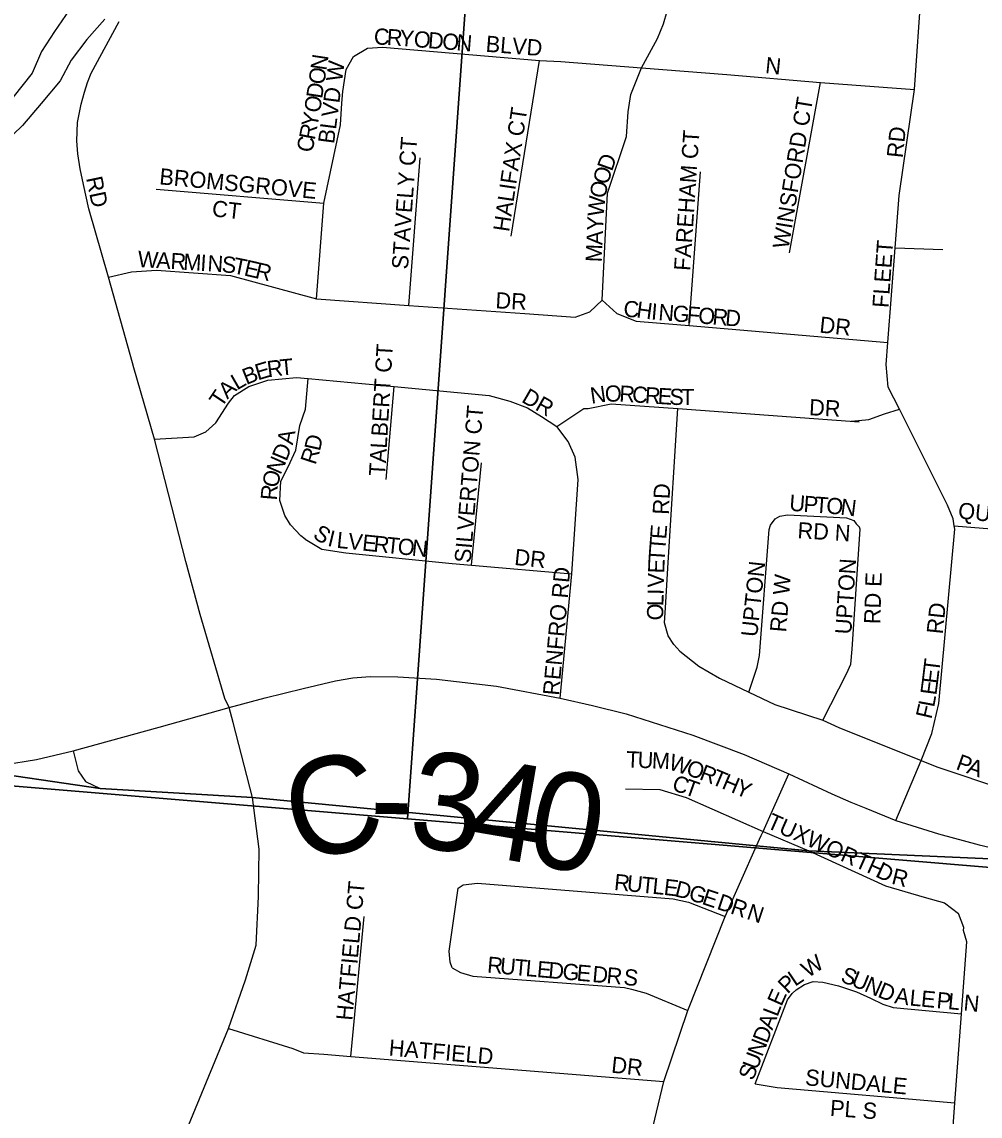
# Model space of a CAD drawing. Extents: x 0 to 34, y 0 to 22.
# Drawn here: x 7.534 to 8.094, y 17.781 to 18.421 of the extents above; entities that cross this region are included whole.
import ezdxf

# ---------------------------------------------------------------- set-up
doc = ezdxf.new("R2010")
doc.units = 0
for name, color, linetype in [('GM_X_City_Street', 7, 'Continuous'), ('GM_X_City_Street_Text', 7, 'Continuous'), ('GM_X_County_Road', 7, 'Continuous'), ('GM_X_County_Road_Text', 7, 'Continuous'), ('GM_X_Major_River', 7, 'Continuous'), ('GM_X_Section', 7, 'Continuous'), ('GM_X_Township', 7, 'Continuous'), ('GM_X_Township_Road', 7, 'Continuous'), ('GM_X_Township_Subdivision', 7, 'Continuous'), ('GM_X_Township_Subdivision_Text', 7, 'Continuous')]:
    doc.layers.add(name, color=color, linetype=linetype)

msp = doc.modelspace()

# ---------------------------------------------------------------- linework, layer by layer
at = {"layer": 'GM_X_City_Street'}
for points in [[(7.87314, 18.25833), (7.87628, 18.32088), (7.88732, 18.35412), (7.88831, 18.36842), (7.88992, 18.37867), (7.8962, 18.39423), (7.90541, 18.41133), (7.9089, 18.42002), (7.91116, 18.42728), (7.91346, 18.4521), (7.91708, 18.51688), (7.91889, 18.54186), (7.91998, 18.57654), (7.92253, 18.59091), (7.92773, 18.60485), (7.93089, 18.61124), (7.9387, 18.62398)], [(8.04039, 18.2075), (8.03909, 18.22079), (8.04009, 18.23371), (8.04437, 18.28898), (8.04675, 18.31968), (8.05567, 18.38157), (8.05978, 18.44059)], [(7.5994, 18.2188), (7.59855, 18.22178), (7.58458, 18.27192), (7.57307, 18.31187), (7.56994, 18.326), (7.56797, 18.33521), (7.56666, 18.34393), (7.566, 18.35149), (7.56649, 18.36234), (7.56847, 18.37302), (7.57044, 18.38009), (7.57224, 18.38569), (7.57438, 18.39111), (7.59082, 18.42136)], [(7.72785, 18.40081), (7.73591, 18.40574), (7.74462, 18.4064), (7.83652, 18.39851), (7.84901, 18.39785), (7.8962, 18.39423), (7.94602, 18.39029), (8.00076, 18.38568), (8.05567, 18.38157)], [(7.70604, 18.25919), (7.71033, 18.31517), (7.72012, 18.36086), (7.72094, 18.37351), (7.72144, 18.38042), (7.72349, 18.39324), (7.72785, 18.40081)], [(7.81983, 18.29584), (7.83652, 18.39851)], [(7.98257, 18.28608), (8.00076, 18.38568)], [(7.76006, 18.25535), (7.7667, 18.34171)], [(7.92401, 18.24354), (7.93059, 18.33344)], [(7.61246, 18.32322), (7.71033, 18.31517)], [(8.04437, 18.28898), (8.0722, 18.28805)], [(7.58458, 18.27192), (7.59806, 18.27504), (7.61253, 18.27587), (7.65593, 18.2729), (7.70604, 18.25919), (7.76006, 18.25535), (7.82799, 18.25052), (7.85743, 18.2484), (7.86582, 18.25165), (7.87314, 18.25833)], [(7.87314, 18.25833), (7.88167, 18.25056), (7.89293, 18.24616), (7.9167, 18.24415), (7.92401, 18.24354), (8.04009, 18.23371)], [(7.65737, 18.0116), (7.6551, 18.02038), (7.65247, 18.02548), (7.63817, 18.07464), (7.62979, 18.1057), (7.61137, 18.17706), (7.5994, 18.2188)]]:
    msp.add_lwpolyline(points, dxfattribs=at)
at = {"layer": 'GM_X_County_Road'}
for points in [[(7.6551, 18.02038), (7.67615, 18.02597), (7.69834, 18.03139), (7.71725, 18.03583), (7.72744, 18.03764), (7.73747, 18.03847), (7.75375, 18.0383), (7.77627, 18.03682), (7.81129, 18.03271), (7.84861, 18.0258), (7.86752, 18.02153), (7.88712, 18.01651), (7.92611, 18.0042), (7.95605, 17.99275), (7.98227, 17.98158), (8.00743, 17.96991), (8.01844, 17.96498), (8.02732, 17.96136), (8.04475, 17.95429), (8.06973, 17.9464), (8.09357, 17.93998), (8.11592, 17.93484), (8.1322, 17.93242), (8.1521, 17.92995)], [(7.5047, 17.9845), (7.52325, 17.98684), (7.54241, 17.98996), (7.56386, 17.99506), (7.61417, 18.00871), (7.6551, 18.02038)], [(7.66872, 17.96769), (7.65737, 18.0116)], [(7.67231, 17.90988), (7.67232, 17.91019), (7.67255, 17.93741), (7.66872, 17.96769)], [(7.58898, 17.60376), (7.58928, 17.60553), (7.59778, 17.66988), (7.6066, 17.70308), (7.62629, 17.76361), (7.65462, 17.83269), (7.66454, 17.86111), (7.67094, 17.88135), (7.67231, 17.90988)]]:
    msp.add_lwpolyline(points, dxfattribs=at)
at = {"layer": 'GM_X_Major_River'}
for points in [[(7.5824, 18.42262), (7.57179, 18.41088), (7.56269, 18.39875), (7.55623, 18.38661), (7.54524, 18.37335), (7.53424, 18.36047), (7.52325, 18.34986)], [(7.5616, 18.42796), (7.55288, 18.41545), (7.5453, 18.4037), (7.53998, 18.39119), (7.5286, 18.37679)]]:
    msp.add_lwpolyline(points, dxfattribs=at)
at = {"layer": 'GM_X_Section'}
for points in [[(7.32396, 19.01244), (7.83199, 18.97493), (7.7594, 17.95531), (7.25608, 17.99704)], [(7.83199, 18.97493), (8.33817, 18.93281), (8.26119, 17.91328), (7.7594, 17.95531)], [(7.25608, 17.99704), (7.7594, 17.95531), (8.26119, 17.91328), (8.28732, 17.91243), (8.21553, 16.97509), (7.19182, 17.04453)]]:
    msp.add_lwpolyline(points, close=True, dxfattribs=at)
at = {"layer": 'GM_X_Township'}
for points in [[(5.51769, 18.13119), (5.87625, 18.1039), (6.03605, 18.09206), (6.63383, 18.04603), (6.72474, 18.03863), (6.7448, 18.03814), (6.76124, 18.03764), (6.90082, 18.02498), (7.39535, 17.98733), (7.4612, 17.98313), (7.48383, 17.98347), (7.50256, 17.98423), (7.57966, 17.97294), (7.66873, 17.96768), (7.96341, 17.93943), (7.99401, 17.9365), (8.15736, 17.9293), (8.25091, 17.92059), (8.28461, 17.91779), (8.63956, 17.89017), (9.29091, 17.83808), (9.37362, 17.83148), (9.4, 17.82945)], [(9.4, 17.82945), (9.37362, 17.83148), (9.29091, 17.83808), (8.63956, 17.89017), (8.28461, 17.91779), (8.25091, 17.92059), (8.15736, 17.9293), (7.99401, 17.9365), (7.96341, 17.93943), (7.66873, 17.96768), (7.57966, 17.97294), (7.50256, 17.98423), (7.48383, 17.98347), (7.4612, 17.98313), (7.39535, 17.98733), (6.90082, 18.02498), (6.76124, 18.03764), (6.7448, 18.03814), (6.72474, 18.03863), (6.63383, 18.04603), (6.03605, 18.09206), (5.87625, 18.1039), (5.51769, 18.13119)]]:
    msp.add_lwpolyline(points, dxfattribs=at)
at = {"layer": 'GM_X_Township_Road'}
msp.add_lwpolyline([(7.56386, 17.99506), (7.5668, 17.98336), (7.57116, 17.97705), (7.57966, 17.97294), (7.66872, 17.96769)], dxfattribs=at)
at = {"layer": 'GM_X_Township_Subdivision'}
for points in [[(7.61137, 18.17706), (7.63466, 18.17846), (7.64153, 18.18139), (7.6473, 18.18662), (7.65469, 18.19828), (7.65815, 18.20275), (7.6666, 18.20796), (7.67765, 18.21158), (7.69435, 18.21321), (7.70132, 18.21256), (7.75144, 18.20788), (7.80713, 18.20268), (7.81921, 18.19945), (7.82938, 18.19549), (7.83764, 18.19042), (7.84663, 18.18458)], [(7.69957, 18.11867), (7.69695, 18.12061), (7.69098, 18.12716), (7.68766, 18.13253), (7.68477, 18.14131), (7.68533, 18.1527), (7.68963, 18.16099), (7.69396, 18.1708), (7.69647, 18.1852), (7.69966, 18.19464), (7.70132, 18.21256)], [(7.74677, 18.15363), (7.75144, 18.20788)], [(8.04475, 17.95429), (8.05954, 17.98931), (8.06585, 18.00502), (8.06995, 18.02267), (8.07925, 18.12446), (8.07888, 18.12659), (8.07821, 18.13055), (8.07493, 18.13858), (8.04685, 18.19461), (8.04039, 18.2075)], [(7.84663, 18.18458), (7.86234, 18.19511), (7.865, 18.19507), (7.87832, 18.1979), (7.91731, 18.19504), (8.02338, 18.18725), (8.01883, 18.18771), (8.02909, 18.18868), (8.03825, 18.19196), (8.04685, 18.19461)], [(7.91845, 18.0533), (7.9151, 18.05715), (7.91177, 18.06214), (7.90962, 18.06977), (7.91014, 18.0785), (7.9117, 18.10506), (7.91731, 18.19504)], [(7.84861, 18.0258), (7.85543, 18.09845), (7.85902, 18.15361), (7.85734, 18.16655), (7.85332, 18.17573), (7.84663, 18.18458)], [(7.79678, 18.10343), (7.80267, 18.16339)], [(7.9589, 18.02921), (7.96381, 18.04385), (7.96506, 18.05066), (7.97079, 18.12426), (7.97159, 18.12691), (7.97431, 18.13066)], [(7.97431, 18.13066), (7.97699, 18.13214), (7.98155, 18.13283), (8.01603, 18.13115), (8.02018, 18.12956), (8.02166, 18.12764)], [(8.00216, 18.01282), (8.01608, 18.04036), (8.01844, 18.04564), (8.01934, 18.05437), (8.02389, 18.12457), (8.02353, 18.12571), (8.02166, 18.12764)], [(8.07888, 18.12659), (8.13236, 18.12218), (8.18831, 18.11757), (8.2432, 18.11304)], [(7.69957, 18.11867), (7.70933, 18.11282), (7.72333, 18.11069), (7.78542, 18.1044), (7.79678, 18.10343), (7.85543, 18.09845)], [(7.91845, 18.0533), (7.92969, 18.04438), (7.94171, 18.03735), (7.9589, 18.02921), (7.97408, 18.02203), (8.00216, 18.01282), (8.01153, 18.00854), (8.05954, 17.98931), (8.06875, 17.98553), (8.10886, 17.97221), (8.15095, 17.96188), (8.23009, 17.95456)], [(7.96608, 17.94542), (7.96717, 17.94786), (7.98227, 17.98158)], [(7.88681, 17.97276), (7.90682, 17.9724), (7.92221, 17.96767), (7.96717, 17.94786)], [(7.90411, 17.56419), (7.89935, 17.57452), (7.89173, 17.59591), (7.89107, 17.602), (7.8894, 17.6157), (7.89053, 17.63885), (7.89332, 17.68094), (7.89454, 17.69917), (7.89971, 17.76176), (7.90926, 17.80167), (7.92328, 17.84308), (7.945, 17.89819), (7.96341, 17.93943), (7.96608, 17.94542)], [(7.96717, 17.94786), (7.99401, 17.9365), (8.03877, 17.91596), (8.06134, 17.90939), (8.07324, 17.90611), (8.08145, 17.89996)], [(7.78885, 17.91469), (7.79191, 17.91654), (7.80026, 17.91755), (7.91459, 17.90851), (7.92365, 17.90646), (7.945, 17.89819)], [(7.78544, 17.86803), (7.78436, 17.87147), (7.78371, 17.87793), (7.78885, 17.91469)], [(7.72619, 17.81631), (7.734, 17.89809)], [(8.05394, 17.57175), (8.06211, 17.72575), (8.06332, 17.72991), (8.06642, 17.73403), (8.06912, 17.73665), (8.0726, 17.74115), (8.07654, 17.75059), (8.07937, 17.78927), (8.08318, 17.84124), (8.08626, 17.88336), (8.08428, 17.88993), (8.0845, 17.89175), (8.08145, 17.89996)], [(7.78544, 17.86803), (7.79033, 17.86529), (7.7975, 17.86328), (7.88608, 17.85655), (7.89024, 17.85572), (7.89892, 17.8533), (7.92328, 17.84308)], [(7.99148, 17.85829), (7.99643, 17.86011), (8.00211, 17.85964), (8.01118, 17.85759), (8.02173, 17.85401), (8.03001, 17.85046), (8.03716, 17.84692), (8.04319, 17.84493), (8.08318, 17.84124)], [(7.9625, 17.80026), (7.98148, 17.84933), (7.98419, 17.85309), (7.9865, 17.85533), (7.99148, 17.85829)], [(7.65462, 17.83269), (7.6922, 17.8209), (7.6986, 17.81852), (7.71034, 17.81757), (7.72619, 17.81631), (7.90926, 17.80167)], [(7.9625, 17.80026), (7.97534, 17.79816), (8.07937, 17.78927)]]:
    msp.add_lwpolyline(points, dxfattribs=at)

# ---------------------------------------------------------------- texts
at = {"layer": 'GM_X_City_Street_Text'}
for s, height, rotation, p in [('C', 0.00947, 358.2025, (7.73957, 18.40785)), ('R', 0.00947, 355.94034, (7.74697, 18.40762)), ('Y', 0.00947, 355.53591, (7.75443, 18.40709)), ('O', 0.00947, 355.53591, (7.76273, 18.40644)), ('D', 0.00947, 355.51411, (7.77104, 18.40579)), ('O', 0.00947, 355.54485, (7.77935, 18.40514)), ('N', 0.00947, 355.53591, (7.78766, 18.40449)), ('BLVD', 0.00947, 355.48872, (7.80479, 18.40367)), ('N', 0.00947, 81.43253, (7.7119, 18.39233)), ('BLVD W', 0.00947, 82.61454, (7.71638, 18.34951)), ('N', 0.00947, 354.29373, (7.96816, 18.39117)), ('O', 0.00947, 81.43253, (7.71066, 18.38409)), ('D', 0.00947, 81.43253, (7.70942, 18.37585)), ('O', 0.00947, 81.29572, (7.70815, 18.36759)), ('WINSFORD CT', 0.0094697, 80.74043, (7.98206, 18.28802)), ('HALIFAX CT', 0.00947, 81.57243, (7.81872, 18.298)), ('Y', 0.00947, 79.13593, (7.70652, 18.35902)), ('R', 0.00947, 79.13486, (7.70511, 18.35166)), ('RD', 0.00947, 83.99338, (8.04883, 18.34124)), ('C', 0.00947, 79.12822, (7.70369, 18.34429)), ('STAVELY CT', 0.00947, 85.914, (7.75954, 18.27619)), ('FAREHAM CT', 0.00947, 86.14289, (7.92453, 18.27535)), ('D', 0.00947, 70.20452, (7.87882, 18.33331)), ('BROMSGROVE', 0.00947, 354.64262, (7.61398, 18.32617)), ('O', 0.00947, 73.11369, (7.87644, 18.32545)), ('RD', 0.00947, 281.88403, (7.57139, 18.32976)), ('O', 0.00947, 78.93201, (7.87491, 18.31752)), ('CT', 0.00947, 353.66247, (7.64471, 18.30748)), ('W', 0.00947, 84.75034, (7.87395, 18.30699)), ('Y', 0.00947, 87.65951, (7.87362, 18.29879)), ('A', 0.00947, 87.65951, (7.87328, 18.29046)), ('M', 0.00947, 87.65951, (7.87287, 18.28047)), ('FLEET', 0.00947, 85.91142, (8.04049, 18.25368)), ('W', 0.00947, 356.48345, (7.60142, 18.27785)), ('A', 0.00947, 356.50235, (7.61224, 18.27718)), ('R', 0.00947, 356.47668, (7.62055, 18.27667)), ('M', 0.00947, 356.49946, (7.62804, 18.27621)), ('I', 0.00947, 356.45639, (7.63802, 18.2756)), ('N', 0.00947, 356.50235, (7.64219, 18.27534)), ('S', 0.00947, 354.44439, (7.65041, 18.27484)), ('T', 0.00947, 348.75436, (7.6568, 18.27423)), ('E', 0.00947, 347.10369, (7.66327, 18.27295)), ('R', 0.00947, 346.99446, (7.66976, 18.27146)), ('DR', 0.00947, 356.98902, (7.81057, 18.25368)), ('C', 0.00947, 358.29961, (7.88552, 18.24856)), ('H', 0.00947, 352.15117, (7.89275, 18.24836)), ('I', 0.00947, 355.07323, (7.90153, 18.24717)), ('N', 0.00947, 355.28569, (7.90572, 18.24681)), ('G', 0.00947, 355.30818, (7.91403, 18.24612)), ('F', 0.00947, 355.29535, (7.92234, 18.24544)), ('O', 0.00947, 355.30818, (7.92898, 18.24489)), ('R', 0.00947, 355.30696, (7.93729, 18.24421)), ('D', 0.00947, 355.29625, (7.94476, 18.2436)), ('DR', 0.00947, 353.98321, (7.99983, 18.2395))]:
    msp.add_text(s, height=height, rotation=rotation, dxfattribs=at).set_placement(p)
at = {"layer": 'GM_X_County_Road_Text'}
for s, rotation, p in [('C', 13.17102, (7.69516, 17.92923)), ('3', 353.66441, (7.75885, 17.93921)), ('4', 350.26304, (7.79275, 17.93547)), ('0', 349.96278, (7.82717, 17.92957)), ('-', 359.13349, (7.73695, 17.93947))]:
    msp.add_text(s, height=0.05682, rotation=rotation, dxfattribs=at).set_placement(p)
at = {"layer": 'GM_X_Township_Subdivision_Text'}
for s, height, rotation, p in [('TALBERT CT', 0.00947, 86.5928, (7.7462, 18.15534)), ('T', 0.00947, 5.36263, (7.68519, 18.21428)), ('B', 0.00947, 21.71573, (7.66509, 18.20876)), ('E', 0.00947, 16.70709, (7.67185, 18.21146)), ('R', 0.00947, 7.62192, (7.67785, 18.21329)), ('L', 0.00947, 29.89061, (7.65964, 18.20559)), ('T', 0.00947, 56.09781, (7.65065, 18.19515)), ('A', 0.00947, 43.00589, (7.654, 18.20025)), ('DR', 0.00947, 330.11776, (7.82544, 18.19919)), ('N', 0.00947, 8.26921, (7.86685, 18.19782)), ('O', 0.00947, 1.18029, (7.87479, 18.199)), ('R', 0.00947, 356.59789, (7.88292, 18.19917)), ('C', 0.00947, 356.37974, (7.8904, 18.19873)), ('R', 0.00947, 356.37974, (7.89789, 18.19825)), ('E', 0.00947, 356.36402, (7.90537, 18.19778)), ('S', 0.00947, 357.59328, (7.91225, 18.19734)), ('T', 0.00947, 359.64433, (7.91928, 18.19706)), ('DR', 0.00947, 356.98902, (7.99391, 18.19117)), ('SILVERTON CT', 0.0094697, 85.33345, (7.7962, 18.10455)), ('A', 0.00947, 78.77046, (7.69224, 18.17347)), ('D', 0.00947, 77.3315, (7.70811, 18.16979)), ('D', 0.00947, 67.95378, (7.68856, 18.16388)), ('N', 0.00947, 66.2705, (7.68509, 18.15597)), ('R', 0.00947, 71.84917, (7.70551, 18.16173)), ('O', 0.00947, 77.37399, (7.68342, 18.1483)), ('R', 0.00947, 85.38153, (7.68287, 18.14117)), ('RD', 0.00947, 86.98841, (7.91204, 18.13283)), ('U', 0.00947, 355.64655, (7.98227, 18.13535)), ('P', 0.00947, 355.67105, (7.99059, 18.13472)), ('T', 0.00947, 355.65159, (7.99723, 18.13422)), ('O', 0.00947, 355.64655, (8.00388, 18.13371)), ('N', 0.00947, 352.94546, (8.01207, 18.13309)), ('QUINCY', 0.00947, 353.65936, (8.08083, 18.13091)), ('RD N', 0.00947, 356.52717, (7.98711, 18.11926)), ('S', 0.00947, 327.43873, (7.70343, 18.11984)), ('I', 0.00947, 346.07774, (7.71213, 18.11493)), ('L', 0.00947, 354.13386, (7.7176, 18.11367)), ('V', 0.00947, 354.08711, (7.72423, 18.11299)), ('E', 0.00947, 354.08463, (7.73252, 18.11213)), ('E', 0.00947, 85.59709, (7.91054, 18.11843)), ('R', 0.00947, 354.08886, (7.73915, 18.11145)), ('T', 0.00947, 354.08824, (7.74661, 18.11068)), ('O', 0.00947, 354.07857, (7.75324, 18.10999)), ('N', 0.00947, 354.09061, (7.76153, 18.10913)), ('T', 0.00947, 85.65158, (7.91004, 18.11179)), ('DR', 0.00947, 353.99459, (7.8215, 18.10367)), ('T', 0.00947, 86.25497, (7.9096, 18.10516)), ('E', 0.00947, 88.03258, (7.90938, 18.09858)), ('UPTON', 0.00947, 83.79542, (7.96371, 18.06126)), ('UPTON', 0.00947, 86.26602, (8.0187, 18.06285)), ('RENFRO RD', 0.00947, 84.87176, (7.84787, 18.02706)), ('V', 0.00947, 88.57409, (7.90917, 18.09027)), ('RD W', 0.00947, 85.23283, (7.9806, 18.06404)), ('RD E', 0.00947, 88.15329, (8.03564, 18.06894)), ('L', 0.00947, 88.57455, (7.9089, 18.07944)), ('I', 0.00947, 88.55697, (7.90907, 18.0861)), ('O', 0.00947, 88.57936, (7.9087, 18.07111)), ('RD', 0.00947, 83.99458, (8.07216, 18.06291)), ('T', 0.00947, 83.0715, (8.07013, 18.04053)), ('E', 0.00947, 83.0965, (8.06933, 18.03391)), ('E', 0.00947, 82.38523, (8.06843, 18.02718)), ('L', 0.00947, 79.58878, (8.06715, 18.02013)), ('F', 0.00947, 76.9378, (8.06554, 18.01318)), ('T', 0.00947, 357.54012, (7.88704, 17.98536)), ('U', 0.00947, 357.52943, (7.8937, 17.98507)), ('M', 0.00947, 357.53512, (7.90202, 17.98471)), ('W', 0.00947, 342.00104, (7.91135, 17.9844)), ('O', 0.00947, 341.42682, (7.92163, 17.98106)), ('P', 0.00947, 340.20832, (8.07941, 17.98438)), ('A', 0.00947, 340.21854, (8.08568, 17.98212)), ('R', 0.00947, 339.1142, (7.92943, 17.97844)), ('T', 0.00947, 337.1637, (7.93636, 17.9758)), ('H', 0.00947, 337.16321, (7.9425, 17.97321)), ('C', 0.00947, 341.51128, (7.91335, 17.97218)), ('T', 0.00947, 340.41601, (7.92041, 17.96981)), ('Y', 0.00947, 337.16321, (7.95018, 17.96998)), ('TUXWORTH', 0.00947, 336.03723, (7.9687, 17.9502)), ('D', 0.00947, 334.0508, (8.0323, 17.92173)), ('R', 0.00947, 345.8847, (8.04176, 17.91737)), ('HATFIELD CT', 0.0094697, 84.86402, (7.72704, 17.83706)), ('R', 0.00947, 354.3329, (7.87981, 17.91368)), ('U', 0.00947, 354.33072, (7.88727, 17.91294)), ('T', 0.00947, 354.30843, (7.89556, 17.91211)), ('L', 0.00947, 354.3253, (7.9022, 17.91145)), ('E', 0.00947, 353.34603, (7.90879, 17.9108)), ('D', 0.00947, 345.7994, (7.91509, 17.91009)), ('G', 0.00947, 342.34609, (7.92302, 17.90808)), ('E', 0.00947, 341.66007, (7.93094, 17.90557)), ('D', 0.00947, 341.56453, (7.93964, 17.90268)), ('R', 0.00947, 341.57549, (7.94754, 17.90004)), ('N', 0.00947, 341.56505, (7.95703, 17.89688)), ('R', 0.00947, 354.89352, (7.80563, 17.86535)), ('U', 0.00947, 354.92477, (7.81311, 17.86468)), ('T', 0.00947, 354.88472, (7.82141, 17.86394)), ('L', 0.00947, 354.9097, (7.82805, 17.86335)), ('E', 0.00947, 354.91193, (7.83469, 17.86276)), ('W', 0.00947, 33.18176, (7.99346, 17.86204)), ('D', 0.00947, 354.90056, (7.84133, 17.86216)), ('G', 0.00947, 354.90229, (7.84963, 17.86142)), ('E', 0.00947, 354.9097, (7.85793, 17.86068)), ('D', 0.00947, 354.90229, (7.86707, 17.85987)), ('R', 0.00947, 354.91115, (7.87537, 17.85913)), ('S', 0.00947, 353.6749, (7.88527, 17.85825)), ('L', 0.00947, 33.8416, (7.98586, 17.85696)), ('S', 0.00947, 338.86833, (8.01195, 17.86023)), ('U', 0.00947, 337.85765, (8.01813, 17.85785)), ('P', 0.00947, 44.92273, (7.98151, 17.85256)), ('N', 0.00947, 336.52584, (8.02579, 17.85473)), ('D', 0.00947, 337.61908, (8.03361, 17.85133)), ('E', 0.00947, 66.17346, (7.97791, 17.84517)), ('A', 0.00947, 350.98994, (8.04364, 17.84751)), ('L', 0.00947, 354.75743, (8.05254, 17.84612)), ('E', 0.00947, 354.63737, (8.05918, 17.84551)), ('P', 0.00947, 354.64432, (8.06831, 17.84465)), ('L', 0.00947, 354.64432, (8.07495, 17.84403)), ('N', 0.00947, 354.63737, (8.08408, 17.84317)), ('L', 0.00947, 69.1061, (7.97558, 17.83906)), ('D', 0.00947, 69.10371, (7.96964, 17.82349)), ('A', 0.00947, 69.09354, (7.97261, 17.83128)), ('HATFIELD', 0.00947, 354.95717, (7.74812, 17.81689)), ('N', 0.00947, 69.10787, (7.96666, 17.81571)), ('DR', 0.00947, 353.99459, (7.87815, 17.80689)), ('U', 0.00947, 69.0833, (7.96369, 17.80792)), ('S', 0.00947, 69.10176, (7.96131, 17.80169)), ('SUNDALE', 0.00947, 354.72585, (7.99148, 17.79952)), ('PL S', 0.00947, 355.76599, (8.00607, 17.7816))]:
    msp.add_text(s, height=height, rotation=rotation, dxfattribs=at).set_placement(p)

doc.saveas('drawing.dxf')
